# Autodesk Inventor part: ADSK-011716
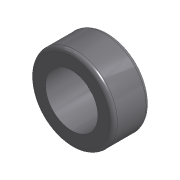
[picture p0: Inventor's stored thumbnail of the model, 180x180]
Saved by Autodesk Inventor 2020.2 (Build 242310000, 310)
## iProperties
Created: 1999-11
Part Number: ADSK-011716
Description: COLLAR,SET,0.750
Document SubType Name: Modeling
Designer: mpflueger
Material: Acier doux
Density: 7.86 g/cm^3
Appearance: Metal-Steel(Polish)
Mass: 53.1822 g
Surface Area: 31.3581 cm^2
Volume: 6.76619 cm^3
Control State: 0
Checked Out: False
Master: False
Shininess: 60.0
Length Units: 11269
Angle Units: 11279
Time Units: 11290
Mass Units: 11283
Length Display Precision: 3
Angle Display Precision: 2
Compacted: True
Dimensions: 32x14x32 mm
Mass: 0,053 kg
VLT_Material: Acier doux
Density: 7.86
Volumn: 7.134102221044877
Area: 31.554311053230887
PropertySet Name: Model Information
Author: mpflueger
Revision Number: -
Title: COLLAR,SET,0.750
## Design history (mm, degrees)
node "Solide1"
  node "Extrusion1" dims "d0" = 14, "d1" = 0
  node "Fillet1" dims "d2" = 1.5
sketch "Sketch1"
  geometry: C1 r 10 at (0, 0); C2 r 16 at (0, 0); 1 further point
  constraints: 2 centre point, 2 coincident
  dimensions: "d3" = 20 diameter of C1; "d4" = 32 diameter of C2
node "Corps solides"
node "Corps surfaciques"
